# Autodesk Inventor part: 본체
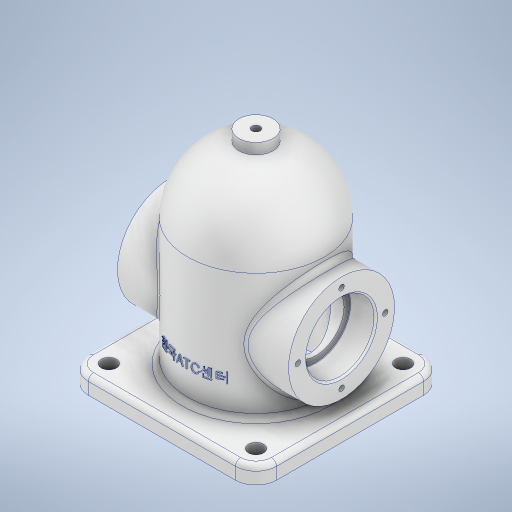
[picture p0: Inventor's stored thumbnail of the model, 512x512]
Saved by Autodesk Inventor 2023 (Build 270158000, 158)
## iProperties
Created: 2025-04
Part Number: 본체
Material: 알루미늄 6061
Document SubType Name: Modeling
Designer: user
Mass: 865.815 g
Surface Area: 801.058 cm^2
Volume: 320.672 cm^3
Density: 2.7 g/cm^3
Appearance: 알루미늄 - 평지
Author: user
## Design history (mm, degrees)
sketch "스케치5"
  geometry: L1 (-55, 55)-(55, 55); L2 (55, 55)-(55, -55); L3 (55, -55)-(-55, -55); L4 (-55, -55)-(-55, 55); L5 (-55, 55)-(55, -55); L6 (55, 55)-(-55, -55); 1 further point
  constraints: 12 end point, 2 midpoint, 2 parallel, 1 horizontal, 1 perpendicular
  dimensions: "d12" = 110 distance of L1.end L2.end; "d13" = 110 distance of L2.end L3.end
extrude "돌출4" new body sketch "스케치5" distance "d14" = 10; taper "d15" = 0 deg
sketch "스케치6"
  geometry: C1 r 40 at (0, 0); 1 further point
  constraints: 1 centre point, 1 coincident
  dimensions: "d16" = 80 diameter of C1
extrude "돌출5" join sketch "스케치6" distance "d17" = 74; taper "d18" = 0 deg
sketch "스케치7"
  geometry: L1 (84, -40)-(84, 40) reference; L2 (-25.895, 0)-(155.372, 0) reference; L3 (84, 40)-(84, 0); L4 (124, 0)-(84, 0); A1 r 40 centre (84, 0) between (124, 0) and (84, 40); 1 further point
  constraints: 4 end point, 2 perpendicular, 2 point on circle, 1 centre point, 1 midpoint, 1 point on line
revolve "회전2" sketch "스케치7" stored, may be unused: angle "d19" = 90 deg
node "작업 평면2"
sketch "스케치8"
  geometry: C1 r 10 at (0, 0); 1 further point
  constraints: 1 centre point, 1 coincident
  dimensions: "d21" = 20 diameter of C1
extrude "돌출6" join sketch "스케치8" stored distance "d22" = 74; taper "d23" = 0 deg
sketch "스케치10"
  geometry: L1 (0, -55)-(0, 55) reference; L2 (0, -55)-(10, -55) reference; C1 r 31 at (48, 0); 1 further point
  constraints: 1 centre point
  dimensions: "d24" = 48 distance from line of L1 C1.centre; "d25" = 55 distance from line of L2 C1.centre; "d26" = 62 diameter of C1
extrude "돌출7" join sketch "스케치10" stored distance "d27" = 100; taper "d28" = 0 deg
sketch "스케치11"
  geometry: C1 r 31 at (0, 0) reference; C2 r 20 at (0, 0); 2 further points
  constraints: 2 coincident, 1 centre point
  dimensions: "d29" = 40 diameter of C2
extrude "돌출8" cut sketch "스케치11" distance "d30" = 15; taper "d31" = 0 deg
sketch "스케치12"
  geometry: C1 r 16.5 at (0, 0); 1 further point
  constraints: 1 centre point
  dimensions: "d32" = 33 diameter of C1
extrude "돌출9" cut sketch "스케치12" stored distance "d33" = 15; taper "d34" = 0 deg
sketch "스케치13" dims "d35" = 51
  geometry: C1 r 20 at (0, 0) reference; 3 further points
  constraints: 1 coincident, 1 vertical alignment, 2 other
hole "구멍1" sketch "스케치13" at (0, 25.5) diameter "d36" = 3.242; stored, may be unused: countersink angle "d40" = 82 deg, drill point angle "d42" = 118 deg; dims "d37" = 8, "d38" = 3.023, "d39" = 2, "d41" = 10
sketch "스케치14"
  geometry: L1 (0, 0)-(32, 0); L2 (-55, 0)-(55, 0) reference; L3 (32, 0)-(32, 84); L4 (32, 84)-(0, 84); L5 (0, 84)-(0, 0); L6 (0, -25.8)-(0, 154.8) reference; L7 (0, 116)-(0, 84); L8 (40, 84)-(-40, 84) reference; A1 r 32 centre (0, 84) between (32, 84) and (0, 116)
  constraints: 10 end point, 3 perpendicular, 2 point on circle, 2 point on line, 1 centre point, 1 coincident, 1 vertical
  dimensions: "d46" = 32 distance of L1.start L1.end; "d47" = 84 distance of L1.end L3.end
revolve "회전3" sketch "스케치14" stored, may be unused: angle "d48" = 90 deg
sketch "스케치15"
  geometry: L1 (43, -43)-(-43, -43); L2 (-43, -43)-(-43, 43); L3 (-43, 43)-(43, 43); L4 (43, 43)-(43, -43); L5 (43, -43)-(-43, 43); L6 (-43, -43)-(43, 43); C1 r 32 at (0, 0) reference; C2 r 4.5 at (-43, -43); C3 r 4.5 at (-43, 43); C4 r 4.5 at (43, 43); C5 r 4.5 at (43, -43); 1 further point
  constraints: 12 end point, 4 centre point, 4 coincident, 2 midpoint, 2 parallel, 1 horizontal, 1 perpendicular
  dimensions: "d49" = 86 distance of L1.end L2.end; "d50" = 86 distance of L2.end L3.end; "d51" = 9 diameter of C5; "d52" = 9 diameter of C2; "d53" = 9 diameter of C3; "d54" = 9 diameter of C4
extrude "돌출10" cut sketch "스케치15" stored distance "d55" = 10; taper "d56" = 0 deg
node "작업 평면3"
sketch "스케치16"
  geometry: L1 (-55, 0)-(55, 0) reference; L2 (0, -25.8)-(0, 154.8) reference; 2 further points
  constraints: 1 point on line, 1 other
  dimensions: "d58" = 30 distance from line of L1 point (0, 30)
feature "엠보싱1" sketch "스케치16" dims "d12" = 110, "d13" = 110, "d59" = 0.5, "d60" = 0
fillet "모깎기1" dims "d61" = 12
fillet "모깎기2" dims "d62" = 3
chamfer "모따기1" distance "d63" = 1; stored, may be unused: second distance "d64" = 2, angle "d65" = 45 deg
fillet "모깎기3" dims "d66" = 0.3
sketch "스케치17"
  geometry: 1 further point
hole "구멍2" sketch "스케치17" at (0, 0) diameter "d67" = 4.917; stored, may be unused: countersink angle "d71" = 90 deg, drill point angle "d73" = 0 deg; dims "d68" = 12, "d69" = 4, "d70" = 2, "d72" = 8
node "솔리드2"
mirror "미러1"
pattern_circular "원형 패턴1" dims angle "d44" = 360 deg
mirror "미러2"
feature "A9D066F2-1C7D-4E18-AEED-F7BC21143FA4" dims "d36" = 3.242, "d37" = 8, "d38" = 3.023, "d39" = 2, "d40" = 82 deg, "d41" = 10, "d42" = 118 deg
other parameters: "d20" = 129, "d57" = 193
